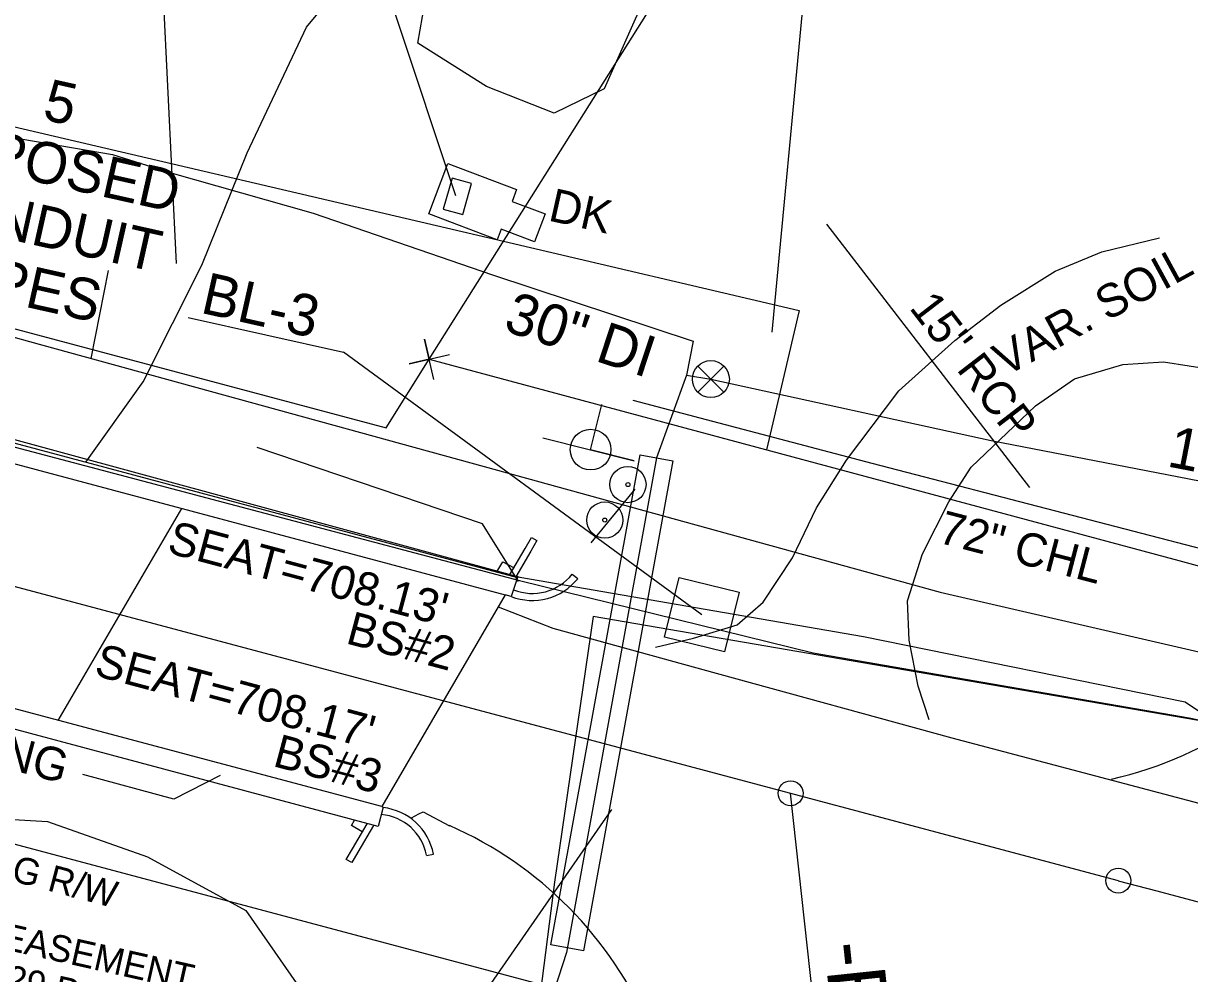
# Model space of a CAD drawing. Extents: x 1784037 to 1786391, y 840555 to 842045.
# Drawn here: x 1785567.5 to 1785708, y 841409.5 to 841524 of the extents above; entities that cross this region are included whole.
import ezdxf

# ---------------------------------------------------------------- set-up
doc = ezdxf.new("R2010")
doc.units = 0
for name, color, linetype in [('CTL Supplemental Horizontal and Vertical CELL', 7, 'Continuous'), ('Exist Building', 7, 'Continuous'), ('Exist Horizontal Alignment', 7, 'Continuous'), ('Exist Horizontal Alignment Direction Label', 7, 'Continuous'), ('Exist Horizontal Alignment Station Label', 7, 'Continuous'), ('Exist Other Culture Area Outline', 7, 'Continuous'), ('Exist Other Culture Area Outline Leader', 7, 'Continuous'), ('Exist Other Culture Area Outline Text', 7, 'Continuous'), ('Exist Other Culture Fence Line', 7, 'Continuous'), ('Exist Other Culture Fence Line Text', 7, 'Continuous'), ('Exist Other Culture Located Object Leader', 7, 'Continuous'), ('Exist Other Culture Sign CELL', 7, 'Continuous'), ('Exist Property Corner CELL', 7, 'Continuous'), ('Exist Property Line', 7, 'Continuous'), ('Exist Property Owner Text', 7, 'Continuous'), ('Exist Right of Way Easement Line', 7, 'Continuous'), ('Exist Right of Way Easement Line Text', 7, 'Continuous'), ('Exist Right of Way Line', 7, 'Continuous'), ('Exist Right of Way Line Text', 7, 'Continuous'), ('Exist Roads EOP', 7, 'Continuous'), ('Exist Roads Soil', 7, 'Continuous'), ('Exist Roads Soil Text', 7, 'Continuous'), ('Exist Structure Major Bridge Seam', 7, 'Continuous'), ('Exist Structure Major Bridge Seat Top Elevation', 7, 'Continuous'), ('Exist Structure Major Bridge WW', 7, 'Continuous'), ('Exist Structure Major Deck Tunnel Box Culvert', 7, 'Continuous'), ('Exist Structure Minor Pipes RCP 15 Inch', 7, 'Continuous'), ('Exist Structure Minor Pipes RCP 15 Inch Text', 7, 'Continuous'), ('Exist Utilities Power Joint Use Telephone CELL', 7, 'Continuous'), ('Exist Utilities Telephone UG Cable SUE LOS B', 7, 'Continuous'), ('Exist Utilities Telephone UG Conduit SUE LOS B', 7, 'Continuous'), ('Exist Utilities Telephone UG Conduit SUE LOS B Leader', 7, 'Continuous'), ('Exist Utilities Telephone UG Conduit SUE LOS B Text', 7, 'Continuous'), ('Exist Utilities Water Test Hole SUE LOS A CELL', 7, 'Continuous'), ('Exist Utilities Water Test Hole SUE LOS A Cogo Number', 7, 'Continuous'), ('Exist Utilities Water UG Line SUE LOS B', 7, 'Continuous'), ('Exist Utilities Water UG Line SUE LOS B Text', 7, 'Continuous'), ('Exist Utilities Water Valve CELL', 7, 'Continuous'), ('Exist Vegetation Woods Line', 7, 'Continuous')]:
    doc.layers.add(name, color=color, linetype=linetype)

msp = doc.modelspace()

# ---------------------------------------------------------------- linework, layer by layer
at = {"layer": 'CTL Supplemental Horizontal and Vertical CELL'}
msp.add_line((1785649.2, 841452.74), (1785649.2, 841452.74), dxfattribs=at)
msp.add_lwpolyline([(1785644.73, 841450.05), (1785646.5, 841457.25), (1785653.71, 841455.48), (1785651.94, 841448.28)], close=True, dxfattribs=at)
at = {"layer": 'Exist Building'}
msp.add_lwpolyline([(1785620.41, 841500.96), (1785621.48, 841504.69), (1785619.13, 841505.36), (1785618.06, 841501.63)], close=True, dxfattribs=at)
at = {"layer": 'Exist Horizontal Alignment'}
for p, q in [((1785423.35, 841494.32), (1785699.38, 841420.72)), ((1785666.66, 841369.39), (1785659.91, 841431.24))]:
    msp.add_line(p, q, dxfattribs=at)
msp.add_arc((1786356.43, 843884.61), 2550, 255.06834, 261.97903, dxfattribs=at)
at = {"layer": 'Exist Horizontal Alignment Station Label'}
for centre in [(1785659.91, 841431.24), (1785699.38, 841420.72)]:
    msp.add_circle(centre, 1.5, dxfattribs=at)
at = {"layer": 'Exist Other Culture Area Outline'}
for p, q in [((1785631.03, 841412.99), (1785641.77, 841472.02)), ((1785645.71, 841471.3), (1785634.96, 841412.27)), ((1785641.77, 841472.02), (1785645.71, 841471.3)), ((1785626.23, 841454.96), (1785625.53, 841455.15)), ((1785610.65, 841429.63), (1785610.83, 841429.58)), ((1785634.96, 841412.27), (1785631.03, 841412.99))]:
    msp.add_line(p, q, dxfattribs=at)
for points in [[(1785629.05, 841497.69), (1785625.05, 841499.2), (1785624.56, 841497.9), (1785616.34, 841501.04), (1785618.63, 841507.12), (1785626.9, 841504), (1785626.35, 841502.55), (1785630.33, 841501.04), (1785629.05, 841497.69)], [(1785469.02, 841496.9), (1785469.69, 841499.28), (1785627.02, 841457.25), (1785626.24, 841454.96)], [(1785610.83, 841429.58), (1785610.22, 841427.22), (1785453, 841469.27), (1785453.66, 841471.48)], [(1785624.53, 841457.92), (1785625.22, 841459.13), (1785626.59, 841458.42)], [(1785608.3, 841426.58), (1785606.99, 841427.35), (1785607.36, 841427.99)]]:
    msp.add_lwpolyline(points, dxfattribs=at)
at = {"layer": 'Exist Other Culture Area Outline Leader'}
msp.add_line((1785638.35, 841429.27), (1785603.64, 841379.39), dxfattribs=at)
msp.add_lwpolyline([(1785591.17, 841433.39), (1785585.61, 841430.53), (1785574.63, 841433.49)], dxfattribs=at)
at = {"layer": 'Exist Other Culture Fence Line'}
msp.add_lwpolyline([(1785640.91, 841478.62), (1785669.69, 841471.03), (1785717.97, 841458.48)], dxfattribs=at)
at = {"layer": 'Exist Other Culture Located Object Leader'}
msp.add_lwpolyline([(1785619.56, 841503.22), (1785605.13, 841546.73)], dxfattribs=at)
at = {"layer": 'Exist Other Culture Sign CELL'}
msp.add_line((1785635.89, 841461.41), (1785641.17, 841467.89), dxfattribs=at)
for centre, radius in [((1785640.31, 841468.43), 2.18), ((1785640.31, 841468.43), 0.24), ((1785637.52, 841464.16), 2.18), ((1785637.52, 841464.16), 0.24)]:
    msp.add_circle(centre, radius, dxfattribs=at)
at = {"layer": 'Exist Property Corner CELL'}
msp.add_line((1785616.38, 841483.53), (1785616.38, 841483.53), dxfattribs=at)
msp.add_lwpolyline([(1785616.93, 841481.1), (1785615.82, 841485.97), (1785616.38, 841483.53), (1785613.94, 841482.98), (1785618.81, 841484.09)], dxfattribs=at)
at = {"layer": 'Exist Property Line'}
msp.add_line((1785616.38, 841483.53), (1785673.13, 841573.7), dxfattribs=at)
at = {"layer": 'Exist Property Owner Text'}
for p, q in [((1785657.7, 841486.78), (1785677.81, 841701.08)), ((1785585.92, 841495.06), (1785581.97, 841576.94))]:
    msp.add_line(p, q, dxfattribs=at)
at = {"layer": 'Exist Right of Way Easement Line'}
for p, q in [((1785379.72, 841555.2), (1785625.32, 841497.74)), ((1785625.32, 841497.74), (1785660.92, 841489.41)), ((1785660.92, 841489.41), (1785656.99, 841472.62))]:
    msp.add_line(p, q, dxfattribs=at)
at = {"layer": 'Exist Right of Way Line'}
for p, q in [((1785431.08, 841523.31), (1785611.18, 841475.28)), ((1785611.18, 841475.28), (1785616.38, 841483.53)), ((1785616.38, 841483.53), (1785706.69, 841459.27)), ((1785415.62, 841465.34), (1785632.32, 841407.55))]:
    msp.add_line(p, q, dxfattribs=at)
msp.add_arc((1786288.21, 843622.47), 2240, 254.95334, 257.91075, dxfattribs=at)
at = {"layer": 'Exist Roads EOP'}
for points in [[(1785624.69, 841453.72), (1785631.28, 841451.15), (1785650.93, 841445.71), (1785679.32, 841437.94), (1785712.6, 841429.12)], [(1785614.23, 841428.29), (1785615.11, 841428.75), (1785615.63, 841428.99)], [(1785615.63, 841428.99), (1785618.83, 841427.34)]]:
    msp.add_lwpolyline(points, dxfattribs=at)
msp.add_ellipse((1785600, 841384.58), major_axis=(-33.42, 32.67), ratio=0.999721, start_param=4.319895, end_param=5.071677, dxfattribs=at)
at = {"layer": 'Exist Roads Soil'}
for points in [[(1785643.65, 841448.84), (1785648.19, 841449.94), (1785653.47, 841451.52), (1785656.6, 841454.27), (1785660.14, 841459.6), (1785663.01, 841465.65), (1785666.63, 841471.37), (1785672.95, 841479.71), (1785679.69, 841485.81), (1785685.24, 841490.06), (1785691.78, 841494.13), (1785697.42, 841496.47), (1785704.35, 841498.18)], [(1785676.59, 841440.08), (1785675.28, 841444.16), (1785674.19, 841449.69), (1785674, 841454.44), (1785675.8, 841460.09), (1785678.97, 841466.36), (1785681.67, 841470.53), (1785685.1, 841473.81), (1785689.43, 841477.92), (1785694.13, 841481.19), (1785699.93, 841482.88), (1785704.85, 841483.21), (1785711, 841482.26)]]:
    msp.add_lwpolyline(points, dxfattribs=at)
msp.add_ellipse((1785689.1, 841476.55), major_axis=(35.72, 27.14), ratio=0.993255, start_param=4.278776, end_param=4.687185, dxfattribs=at)
at = {"layer": 'Exist Structure Major Bridge Seam'}
msp.add_line((1785571.66, 841440.03), (1785586.58, 841465.54), dxfattribs=at)
at = {"layer": 'Exist Structure Major Bridge WW'}
for p, q in [((1785633.6, 841457.63), (1785634.26, 841457.1)), ((1785616.04, 841423.76), (1785616.87, 841423.92))]:
    msp.add_line(p, q, dxfattribs=at)
for points in [[(1785626.06, 841457.51), (1785627.92, 841460.73), (1785628.68, 841462.05), (1785629.33, 841461.68), (1785628.6, 841460.41), (1785626.81, 841457.31)], [(1785609.64, 841427.38), (1785607.76, 841424.15), (1785607.03, 841422.89), (1785606.38, 841423.27), (1785607.11, 841424.53), (1785608.89, 841427.58)]]:
    msp.add_lwpolyline(points, dxfattribs=at)
for centre, major_axis, ratio, start_param, end_param in [((1785628.8, 841461.47), (5.88, -3.8), 0.999945, 4.91124, 6.182267), ((1785628.8, 841461.47), (6.07, -1.01), 0.999845, 4.497402, 5.774502), ((1785610.07, 841422.63), (-6.71, -1.72), 0.999951, 3.078012, 4.354641), ((1785610.07, 841422.64), (5.91, -1.41), 0.9994, 0.420914, 1.718162)]:
    msp.add_ellipse(centre, major_axis=major_axis, ratio=ratio, start_param=start_param, end_param=end_param, dxfattribs=at)
at = {"layer": 'Exist Structure Major Deck Tunnel Box Culvert'}
for p, q in [((1785469.05, 841496.9), (1785625.53, 841455.15)), ((1785610.65, 841429.63), (1785454.32, 841471.31)), ((1785625.53, 841455.15), (1785610.65, 841429.63))]:
    msp.add_line(p, q, dxfattribs=at)
at = {"layer": 'Exist Structure Minor Pipes RCP 15 Inch'}
msp.add_line((1785688.72, 841468.07), (1785664.29, 841499.82), dxfattribs=at)
at = {"layer": 'Exist Utilities Power Joint Use Telephone CELL'}
msp.add_line((1785635.82, 841472.64), (1785635.82, 841472.64), dxfattribs=at)
msp.add_lwpolyline([(1785630.06, 841474.07), (1785641.05, 841471.3), (1785635.81, 841472.62), (1785637.18, 841478.1)], dxfattribs=at)
msp.add_circle((1785635.82, 841472.64), 2.45, dxfattribs=at)
at = {"layer": 'Exist Utilities Telephone UG Cable SUE LOS B'}
msp.add_lwpolyline([(1785711.37, 841439.59), (1785636.12, 841452.54), (1785631.47, 841420.52), (1785628.05, 841393.86), (1785626.31, 841380.54), (1785639.73, 841341.8), (1785645.13, 841327.26), (1785644.61, 841325.43)], dxfattribs=at)
at = {"layer": 'Exist Utilities Telephone UG Conduit SUE LOS B'}
for points in [[(1784928.05, 841589.68), (1784977.44, 841588.79), (1785045.59, 841585.65), (1785096.16, 841584.08), (1785147.53, 841579.79), (1785223.95, 841569.41), (1785281.27, 841561.43), (1785341.54, 841551.4), (1785414.22, 841535.89), (1785463.58, 841519.55), (1785545.63, 841491.96), (1785568.22, 841485.69), (1785622.97, 841470.63), (1785677.94, 841455.48), (1785722.13, 841445.28), (1785786.53, 841428.1), (1785793.16, 841426.49), (1785850.79, 841412.3)], [(1785005.87, 841580.26), (1785008.36, 841581.93), (1785062.26, 841579.21), (1785093.39, 841578.51), (1785144.97, 841574.87), (1785185.01, 841564.27), (1785220.42, 841557.21), (1785276.71, 841548.86), (1785332.97, 841538.64), (1785392.81, 841526.16), (1785444.96, 841509.52), (1785469.05, 841500.37), (1785627.28, 841457.29), (1785668.69, 841450.12), (1785707.44, 841442.24), (1785711.37, 841439.59)], [(1785005.87, 841580.26), (1785047.36, 841578.88), (1785094.69, 841575.39), (1785155.58, 841571.08), (1785221.47, 841554.76), (1785277.4, 841546.34), (1785356.59, 841532.89), (1785417.24, 841517.03), (1785459.64, 841501.34), (1785469.4, 841498.6), (1785627.24, 841456.89), (1785662.63, 841448.15), (1785707.93, 841440.35), (1785711.37, 841439.59)]]:
    msp.add_lwpolyline(points, dxfattribs=at)
at = {"layer": 'Exist Utilities Telephone UG Conduit SUE LOS B Leader'}
msp.add_line((1785575.64, 841483.61), (1785577.75, 841494.22), dxfattribs=at)
msp.add_lwpolyline([(1785627.11, 841456.77), (1785622.78, 841463.71), (1785595.66, 841472.89)], dxfattribs=at)
at = {"layer": 'Exist Utilities Water Test Hole SUE LOS A CELL'}
for p in [(1785587.33, 841488.57), (1785649.2, 841452.74)]:
    msp.add_line(p, (1785606.06, 841484.37), dxfattribs=at)
at = {"layer": 'Exist Utilities Water Test Hole SUE LOS A Cogo Number'}
msp.add_lwpolyline([(1785575, 841471.15), (1785581.9, 841480.8), (1785588.96, 841494.85), (1785594.44, 841508.4), (1785601.59, 841523.55), (1785620.36, 841546.21), (1785634.84, 841566.58), (1785649.13, 841585.09)], dxfattribs=at)
at = {"layer": 'Exist Utilities Water UG Line SUE LOS B'}
for points in [[(1785467.8, 841530.07), (1785514.16, 841519.18), (1785515.92, 841518.85), (1785578.2, 841508.18), (1785585.11, 841506.05), (1785602.38, 841501.15), (1785623.99, 841493.69), (1785648.17, 841485.72), (1785647.36, 841481.63), (1785643.74, 841471.66), (1785632.89, 841412.04), (1785624.66, 841386.69), (1785631.47, 841371.31), (1785643.26, 841344.47)], [(1785647.36, 841481.63), (1785650.3, 841481.14), (1785684.07, 841473.74), (1785731.76, 841464.52), (1785760.43, 841458.68), (1785766.54, 841479.52), (1785772.67, 841514.87), (1785775.88, 841514.16), (1785791.52, 841511.53)]]:
    msp.add_lwpolyline(points, dxfattribs=at)
at = {"layer": 'Exist Utilities Water Valve CELL'}
msp.add_lwpolyline([(1785651.87, 841482.71), (1785648.72, 841479.56), (1785650.3, 841481.14), (1785651.87, 841479.56), (1785648.72, 841482.71)], dxfattribs=at)
msp.add_circle((1785650.3, 841481.14), 2.23, dxfattribs=at)
at = {"layer": 'Exist Vegetation Woods Line'}
for points in [[(1785708.87, 841577.98), (1785692.06, 841586.35), (1785687.02, 841587.27), (1785683.91, 841581.43), (1785670.36, 841563.67), (1785661.02, 841551.51), (1785649.12, 841539.35), (1785642.49, 841527.53), (1785637.43, 841516.12), (1785631.42, 841513.16), (1785623.26, 841516.39), (1785614.98, 841521.61), (1785616.13, 841528.09), (1785623.91, 841545.25), (1785634.78, 841563.53), (1785650.44, 841583.47), (1785668.27, 841601.63), (1785682.99, 841616.36), (1785702.32, 841635.46)], [(1785557.37, 841428.59), (1785570.39, 841427.86), (1785582.44, 841423.57), (1785594.29, 841417.1), (1785603.83, 841403.39), (1785611, 841389.09), (1785623.68, 841374.66), (1785634.97, 841362.92), (1785639.47, 841354.38), (1785646.71, 841344.25), (1785647.83, 841335.14), (1785641.06, 841324.9), (1785626.76, 841314.89), (1785616.63, 841297.25), (1785612.72, 841286.96), (1785601.71, 841277.8), (1785592.82, 841274.48), (1785585.4, 841280.1), (1785573.09, 841297.82), (1785560.8, 841304.2)]]:
    msp.add_lwpolyline(points, dxfattribs=at)

# ---------------------------------------------------------------- texts
at = {"layer": 'Exist Horizontal Alignment Direction Label'}
msp.add_text('-EY1-', height=7, rotation=276.0366, dxfattribs=at).set_placement((1785663.92, 841413.1))
at = {"layer": 'Exist Other Culture Area Outline Text'}
for s, rotation, p in [('DK', 347.3599, (1785630.58, 841500.27)), ('CONC RAILING', 345.0566, (1785534.94, 841442.35))]:
    msp.add_text(s, height=4, rotation=rotation, dxfattribs=at).set_placement(p)
at = {"layer": 'Exist Other Culture Fence Line Text'}
msp.add_text('72" CHL', height=4, rotation=345.4286, dxfattribs=at).set_placement((1785677.52, 841461.48))
at = {"layer": 'Exist Right of Way Easement Line Text'}
for s, p in [('UTILITY EASEMENT', (1785547.93, 841416.29)), ('REF. DB 3929 PG 378', (1785542.87, 841412.5))]:
    msp.add_text(s, height=3.2, rotation=347.3599, dxfattribs=at).set_placement(p)
at = {"layer": 'Exist Right of Way Line Text'}
msp.add_text('EXISTING R/W', height=3.2, rotation=345.0683, dxfattribs=at).set_placement((1785549.8, 841425.02))
at = {"layer": 'Exist Roads Soil Text'}
msp.add_text('VAR. SOIL', height=4, rotation=28.6024, dxfattribs=at).set_placement((1785685.77, 841481.4))
at = {"layer": 'Exist Structure Major Bridge Seat Top Elevation'}
for s, p in [("SEAT=708.13'", (1785584.64, 841460.26)), ('BS#2', (1785606.18, 841449.34)), ("SEAT=708.17'", (1785575.86, 841445.47)), ('BS#3', (1785597.39, 841434.55))]:
    msp.add_text(s, height=4, rotation=345.0756, dxfattribs=at).set_placement(p)
at = {"layer": 'Exist Structure Minor Pipes RCP 15 Inch Text'}
msp.add_text('15" RCP', height=4, rotation=307.5848, dxfattribs=at).set_placement((1785674.11, 841489.71))
at = {"layer": 'Exist Utilities Telephone UG Conduit SUE LOS B Text'}
for s, p in [('5', (1785569.63, 841512.47)), ('EXPOSED', (1785554.16, 841508.25)), ('CONDUIT', (1785553.71, 841500.67)), ('PIPES', (1785556.99, 841492.25))]:
    msp.add_text(s, height=5, rotation=347.3599, dxfattribs=at).set_placement(p)
at = {"layer": 'Exist Utilities Water Test Hole SUE LOS A CELL'}
msp.add_text('BL-3', height=5, rotation=347.3599, dxfattribs=at).set_placement((1785588.67, 841489.16))
at = {"layer": 'Exist Utilities Water UG Line SUE LOS B Text'}
for s, rotation, p in [('30" DI', 341.7277, (1785625.14, 841487.04)), ('12" DI', 349.053, (1785705.13, 841470.65))]:
    msp.add_text(s, height=5, rotation=rotation, dxfattribs=at).set_placement(p)

doc.saveas('drawing.dxf')
